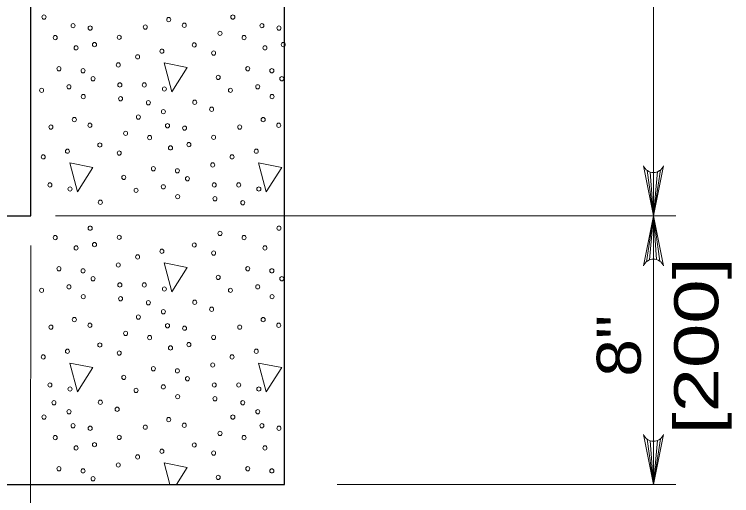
# Model space of a CAD drawing. Extents: x -410.5 to -376.5, y 1617.6 to 1661.6.
# Drawn here: x -401.689 to -399.153, y 1621.375 to 1623.076 of the extents above; entities that cross this region are included whole.
import ezdxf
from ezdxf.enums import TextEntityAlignment as Align

# ---------------------------------------------------------------- set-up
doc = ezdxf.new("R2010")
doc.units = 0
doc.header["$LTSCALE"] = 0.062
doc.layers.add('1', color=7, linetype='Continuous', lineweight=13)

msp = doc.modelspace()

# ---------------------------------------------------------------- linework, layer by layer
at = {"layer": '1'}
for p, q in [((-399.42975, 1626.3615), (-399.42975, 1621.41433)), ((-400.82575, 1622.55058), (-400.79875, 1622.44817)), ((-399.45217, 1622.52408), (-399.42975, 1622.36383)), ((-399.44108, 1622.51858), (-399.42975, 1622.36383)), ((-399.40492, 1622.52592), (-399.42975, 1622.36383)), ((-399.41533, 1622.51983), (-399.42975, 1622.36383)), ((-399.42975, 1622.517), (-399.42975, 1622.36383)), ((-401.5435, 1622.36383), (-400.40392, 1622.36383)), ((-399.35108, 1622.36383), (-400.40392, 1622.36383)), ((-399.4545, 1622.20167), (-399.42975, 1622.36383)), ((-399.44408, 1622.20783), (-399.42975, 1622.36383)), ((-399.42975, 1622.21067), (-399.42975, 1622.36383)), ((-399.41842, 1622.209), (-399.42975, 1622.36383)), ((-399.40733, 1622.20358), (-399.42975, 1622.36383)), ((-401.631, 1622.259), (-401.63283, 1620.696)), ((-400.82575, 1621.84383), (-400.79875, 1621.7415)), ((-399.45217, 1621.57458), (-399.42975, 1621.41433)), ((-399.40492, 1621.5765), (-399.42975, 1621.41433)), ((-399.44108, 1621.56917), (-399.42975, 1621.41433)), ((-399.41533, 1621.57033), (-399.42975, 1621.41433)), ((-399.42975, 1621.5675), (-399.42975, 1621.41433)), ((-401.15942, 1621.49058), (-401.13933, 1621.41433)), ((-399.35108, 1621.41433), (-400.54767, 1621.41433))]:
    msp.add_line(p, q, dxfattribs=at)
at = {"layer": '1', "lineweight": 25}
for points in [[(-405.35992, 1621.41425), (-400.73433, 1621.41425), (-400.73433, 1626.3615), (-405.35992, 1626.3615)], [(-404.46308, 1625.41208), (-404.46308, 1622.36375), (-401.63108, 1622.36375), (-401.63108, 1625.41208)]]:
    msp.add_lwpolyline(points, close=True, dxfattribs=at)
at = {"layer": '1'}
for points in [[(-401.15942, 1622.90392), (-401.13242, 1622.80158), (-401.0775, 1622.888)], [(-401.49325, 1622.55058), (-401.46625, 1622.44817), (-401.41125, 1622.53458)], [(-401.15942, 1622.19725), (-401.13242, 1622.09483), (-401.0775, 1622.18125)], [(-401.49325, 1621.84383), (-401.46625, 1621.7415), (-401.41125, 1621.82792)]]:
    msp.add_lwpolyline(points, close=True, dxfattribs=at)
for points in [[(-400.79875, 1622.44817), (-400.74375, 1622.53458), (-400.82575, 1622.55058)], [(-399.39433, 1622.54083), (-399.42975, 1622.36383), (-399.46508, 1622.54083)], [(-399.46508, 1622.18683), (-399.42975, 1622.36383), (-399.39433, 1622.18683)], [(-400.79875, 1621.7415), (-400.74375, 1621.82792), (-400.82575, 1621.84383)], [(-399.39433, 1621.59133), (-399.42975, 1621.41433), (-399.46508, 1621.59133)], [(-401.11583, 1621.41433), (-401.0775, 1621.47458), (-401.15942, 1621.49058)]]:
    msp.add_lwpolyline(points, dxfattribs=at)
for centre, start, end in [((-399.42975, 1622.5551), 202.08782, 337.91395), ((-399.42968, 1622.17251), 22.08782, 157.91395), ((-399.42975, 1621.60564), 202.08782, 337.91395)]:
    msp.add_arc(centre, 0.0382, start, end, dxfattribs=at)
for centre, major_axis in [((-401.58421, 1623.06607), (0, 0.00756)), ((-400.9167, 1623.06607), (0, 0.00756)), ((-401.48142, 1623.03556), (0, 0.00756)), ((-401.14316, 1623.05718), (0, -0.00756)), ((-401.0882, 1623.03715), (0, -0.00756)), ((-400.81391, 1623.03556), (0, 0.00756)), ((-401.42106, 1623.02691), (0, -0.00756)), ((-401.22609, 1623.0305), (0, -0.00756)), ((-400.75355, 1623.02691), (0, -0.00756)), ((-401.54455, 1622.99357), (0, 0.00756)), ((-401.31832, 1622.99446), (0, -0.00756)), ((-400.96204, 1623.00853), (0, 0.00756)), ((-400.87704, 1622.99357), (0, 0.00756)), ((-401.40577, 1622.96878), (0, -0.00756)), ((-401.0531, 1622.96748), (0, 0.00756)), ((-400.73826, 1622.96878), (0, -0.00756)), ((-401.47068, 1622.9573), (0, -0.00756)), ((-401.16752, 1622.94552), (0, -0.00756)), ((-400.98457, 1622.93886), (0, 0.00756)), ((-400.80317, 1622.9573), (0, -0.00756)), ((-401.25318, 1622.92549), (0, -0.00756)), ((-401.53131, 1622.88356), (0, -0.00756)), ((-401.3216, 1622.89687), (0, -0.00756)), ((-400.8638, 1622.88356), (0, -0.00756)), ((-401.44626, 1622.8762), (0, -0.00756)), ((-400.77875, 1622.8762), (0, -0.00756)), ((-401.41083, 1622.84823), (0, -0.00756)), ((-400.96833, 1622.853), (0, -0.00756)), ((-400.74332, 1622.84823), (0, -0.00756)), ((-401.59256, 1622.80718), (0, -0.00756)), ((-401.49616, 1622.81961), (0, -0.00756)), ((-401.31621, 1622.82626), (0, -0.00756)), ((-401.22965, 1622.82626), (0, 0.00756)), ((-401.15851, 1622.81195), (0, -0.00756)), ((-400.92505, 1622.80718), (0, -0.00756)), ((-400.82865, 1622.81961), (0, -0.00756)), ((-401.44537, 1622.78492), (0, -0.00756)), ((-400.77786, 1622.78492), (0, -0.00756)), ((-401.31354, 1622.77762), (0, -0.00756)), ((-401.21525, 1622.76331), (0, 0.00756)), ((-401.05126, 1622.76519), (0, -0.00756)), ((-401.16213, 1622.7318), (0, 0.00756)), ((-400.9918, 1622.7404), (0, -0.00756)), ((-401.25046, 1622.71272), (0, 0.00756)), ((-401.47691, 1622.70383), (0, -0.00756)), ((-401.42195, 1622.6838), (0, -0.00756)), ((-401.14766, 1622.68221), (0, 0.00756)), ((-400.8094, 1622.70383), (0, -0.00756)), ((-400.75444, 1622.6838), (0, -0.00756)), ((-401.55985, 1622.67715), (0, -0.00756)), ((-401.29579, 1622.65518), (0, 0.00756)), ((-401.08731, 1622.67356), (0, -0.00756)), ((-400.89234, 1622.67715), (0, -0.00756)), ((-401.2108, 1622.64022), (0, 0.00756)), ((-400.98457, 1622.64111), (0, -0.00756)), ((-401.38685, 1622.61413), (0, 0.00756)), ((-401.13693, 1622.60395), (0, -0.00756)), ((-401.07201, 1622.61543), (0, -0.00756)), ((-401.50127, 1622.59217), (0, -0.00756)), ((-401.31832, 1622.58551), (0, 0.00756)), ((-400.83377, 1622.59217), (0, -0.00756)), ((-401.58694, 1622.57214), (0, -0.00756)), ((-400.91943, 1622.57214), (0, -0.00756)), ((-401.19756, 1622.53021), (0, -0.00756)), ((-400.98785, 1622.54352), (0, -0.00756)), ((-401.11251, 1622.52285), (0, -0.00756)), ((-401.30208, 1622.49965), (0, -0.00756)), ((-401.07707, 1622.49488), (0, -0.00756)), ((-401.56341, 1622.47291), (0, 0.00756)), ((-401.49226, 1622.4586), (0, -0.00756)), ((-401.2588, 1622.45383), (0, -0.00756)), ((-401.1624, 1622.46626), (0, -0.00756)), ((-400.98245, 1622.47291), (0, -0.00756)), ((-400.8959, 1622.47291), (0, 0.00756)), ((-400.82476, 1622.4586), (0, -0.00756)), ((-401.11162, 1622.43157), (0, -0.00756)), ((-401.38502, 1622.41184), (0, -0.00756)), ((-400.97978, 1622.42427), (0, -0.00756)), ((-400.88149, 1622.40996), (0, 0.00756)), ((-401.42106, 1622.32021), (0, -0.00756)), ((-400.96204, 1622.30183), (0, 0.00756)), ((-400.75355, 1622.32021), (0, -0.00756)), ((-401.54455, 1622.28687), (0, 0.00756)), ((-401.31832, 1622.28776), (0, -0.00756)), ((-400.87704, 1622.28687), (0, 0.00756)), ((-401.47068, 1622.2506), (0, -0.00756)), ((-401.40577, 1622.26208), (0, -0.00756)), ((-401.0531, 1622.26078), (0, 0.00756)), ((-400.80317, 1622.2506), (0, -0.00756)), ((-401.16752, 1622.23882), (0, -0.00756)), ((-400.98457, 1622.23216), (0, 0.00756)), ((-401.25318, 1622.21879), (0, -0.00756)), ((-401.53131, 1622.17686), (0, -0.00756)), ((-401.3216, 1622.19017), (0, -0.00756)), ((-400.8638, 1622.17686), (0, -0.00756)), ((-401.44626, 1622.1695), (0, -0.00756)), ((-400.77875, 1622.1695), (0, -0.00756)), ((-401.41083, 1622.14153), (0, -0.00756)), ((-400.96833, 1622.1463), (0, -0.00756)), ((-400.74332, 1622.14153), (0, -0.00756)), ((-401.59256, 1622.10048), (0, -0.00756)), ((-401.49616, 1622.11291), (0, -0.00756)), ((-401.31621, 1622.11956), (0, -0.00756)), ((-401.22965, 1622.11956), (0, 0.00756)), ((-401.15851, 1622.10525), (0, -0.00756)), ((-400.92505, 1622.10048), (0, -0.00756)), ((-400.82865, 1622.11291), (0, -0.00756)), ((-401.44537, 1622.07822), (0, -0.00756)), ((-401.31354, 1622.07092), (0, -0.00756)), ((-400.77786, 1622.07822), (0, -0.00756)), ((-401.21525, 1622.05661), (0, 0.00756)), ((-401.05126, 1622.05849), (0, -0.00756)), ((-401.16213, 1622.0251), (0, 0.00756)), ((-400.9918, 1622.0337), (0, -0.00756)), ((-401.47691, 1621.99713), (0, -0.00756)), ((-401.25046, 1622.00602), (0, 0.00756)), ((-400.8094, 1621.99713), (0, -0.00756)), ((-401.55985, 1621.97045), (0, -0.00756)), ((-401.42195, 1621.9771), (0, -0.00756)), ((-401.14766, 1621.97551), (0, 0.00756)), ((-400.89234, 1621.97045), (0, -0.00756)), ((-400.75444, 1621.9771), (0, -0.00756)), ((-401.29579, 1621.94848), (0, 0.00756)), ((-401.08731, 1621.96686), (0, -0.00756)), ((-401.2108, 1621.93352), (0, 0.00756)), ((-400.98457, 1621.93441), (0, -0.00756)), ((-401.38685, 1621.90743), (0, 0.00756)), ((-401.13693, 1621.89725), (0, -0.00756)), ((-401.07201, 1621.90873), (0, -0.00756)), ((-401.50127, 1621.88547), (0, -0.00756)), ((-401.31832, 1621.87881), (0, 0.00756)), ((-400.83377, 1621.88547), (0, -0.00756)), ((-401.58694, 1621.86544), (0, -0.00756)), ((-400.91943, 1621.86544), (0, -0.00756)), ((-401.19756, 1621.82351), (0, -0.00756)), ((-400.98785, 1621.83682), (0, -0.00756)), ((-401.30208, 1621.79295), (0, -0.00756)), ((-401.11251, 1621.81615), (0, -0.00756)), ((-401.07707, 1621.78818), (0, -0.00756)), ((-401.56341, 1621.76621), (0, 0.00756)), ((-401.49226, 1621.7519), (0, -0.00756)), ((-401.2588, 1621.74713), (0, -0.00756)), ((-401.1624, 1621.75956), (0, -0.00756)), ((-400.98245, 1621.76621), (0, -0.00756)), ((-400.8959, 1621.76621), (0, 0.00756)), ((-400.82476, 1621.7519), (0, -0.00756)), ((-401.11162, 1621.72487), (0, -0.00756)), ((-400.97978, 1621.71757), (0, -0.00756)), ((-401.549, 1621.70326), (0, 0.00756)), ((-401.38502, 1621.70514), (0, -0.00756)), ((-400.88149, 1621.70326), (0, 0.00756)), ((-401.49588, 1621.67175), (0, 0.00756)), ((-401.32555, 1621.68035), (0, -0.00756)), ((-400.82837, 1621.67175), (0, 0.00756)), ((-401.58421, 1621.65267), (0, 0.00756)), ((-401.14316, 1621.64378), (0, -0.00756)), ((-400.9167, 1621.65267), (0, 0.00756)), ((-401.48142, 1621.62216), (0, 0.00756)), ((-401.22609, 1621.6171), (0, -0.00756)), ((-401.0882, 1621.62375), (0, -0.00756)), ((-400.81391, 1621.62216), (0, 0.00756)), ((-401.42106, 1621.61351), (0, -0.00756)), ((-400.96204, 1621.59513), (0, 0.00756)), ((-400.75355, 1621.61351), (0, -0.00756)), ((-401.54455, 1621.58017), (0, 0.00756)), ((-401.31832, 1621.58106), (0, -0.00756)), ((-400.87704, 1621.58017), (0, 0.00756)), ((-401.47068, 1621.5439), (0, -0.00756)), ((-401.40577, 1621.55538), (0, -0.00756)), ((-401.0531, 1621.55408), (0, 0.00756)), ((-400.80317, 1621.5439), (0, -0.00756)), ((-401.16752, 1621.53212), (0, -0.00756)), ((-400.98457, 1621.52546), (0, 0.00756)), ((-401.25318, 1621.51209), (0, -0.00756)), ((-401.53131, 1621.47016), (0, -0.00756)), ((-401.44626, 1621.4628), (0, -0.00756)), ((-401.3216, 1621.48347), (0, -0.00756)), ((-400.8638, 1621.47016), (0, -0.00756)), ((-400.77875, 1621.4628), (0, -0.00756)), ((-400.96833, 1621.4396), (0, -0.00756)), ((-401.41083, 1621.43483), (0, -0.00756))]:
    msp.add_ellipse(centre, major_axis=major_axis, ratio=0.944543, dxfattribs=at)

# ---------------------------------------------------------------- texts
for s, width, p in [('[200]', 1.35, (-399.20025, 1621.90442)), ('8"', 1.15, (-399.47425, 1621.90442))]:
    msp.add_text(s, height=0.156, rotation=90, dxfattribs=dict(at, width=width)).set_placement(p, align=Align.CENTER)

doc.saveas('drawing.dxf')
